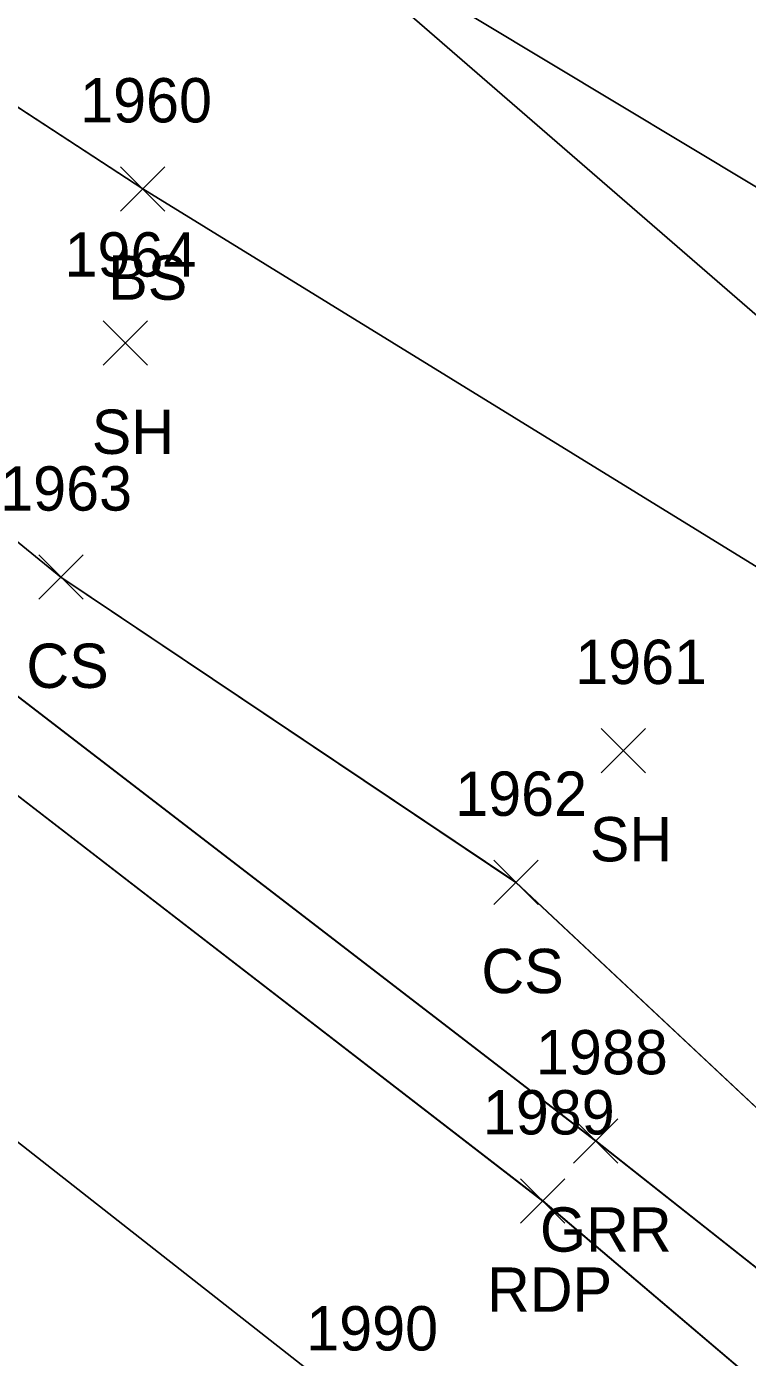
# Model space of a CAD drawing. Extents: x 1415642 to 1422021, y 544543 to 547232.
# Drawn here: x 1416123.6 to 1416156.1, y 546840.3 to 546900.4 of the extents above; entities that cross this region are included whole.
import ezdxf

# ---------------------------------------------------------------- set-up
doc = ezdxf.new("R2010")
doc.units = 0
for name, color, linetype in [('L_A', 7, 'Continuous'), ('L_I', 7, 'Continuous'), ('L_TIC', 7, 'Continuous'), ('LELB', 7, 'Continuous'), ('P_A', 7, 'Continuous'), ('P_I', 7, 'Continuous'), ('P_TIC', 7, 'Continuous'), ('PET', 7, 'Continuous'), ('PRC', 7, 'Continuous'), ('R_A', 7, 'Continuous'), ('R_I', 7, 'Continuous'), ('R_TIC', 7, 'Continuous'), ('RGR', 7, 'Continuous')]:
    doc.layers.add(name, color=color, linetype=linetype)

msp = doc.modelspace()

# ---------------------------------------------------------------- linework, layer by layer
at = {"layer": 'L_TIC'}
for points in [[(1416127.857, 546892.051), (1416129.857, 546894.051)], [(1416129.857, 546892.051), (1416127.857, 546894.051)], [(1416127.067, 546885.094), (1416129.067, 546887.094)], [(1416129.067, 546885.094), (1416127.067, 546887.094)], [(1416124.164, 546874.535), (1416126.164, 546876.535)], [(1416126.164, 546874.535), (1416124.164, 546876.535)], [(1416149.539, 546866.71), (1416151.539, 546868.71)], [(1416151.539, 546866.71), (1416149.539, 546868.71)], [(1416144.693, 546860.764), (1416146.693, 546862.764)], [(1416146.693, 546860.764), (1416144.693, 546862.764)]]:
    msp.add_lwpolyline(points, dxfattribs=at)
at = {"layer": 'LELB'}
for points in [[(1416166.265, 546865.71), (1416159.514, 546874.184), (1416128.857, 546893.051), (1416099.942, 546911.946), (1416080.109, 546927.167), (1416051.607, 546951.273), (1416024.788, 546978.542), (1415989.847, 547005.498), (1415949.916, 547022.61), (1415918.775, 547047.798), (1415880.242, 547071.016), (1415848.802, 547092.398)], [(1416166.265, 546865.71), (1416159.513, 546874.184), (1416128.861, 546893.052), (1416099.946, 546911.942), (1416080.11, 546927.168), (1416051.609, 546951.273), (1416024.792, 546978.539), (1415989.849, 547005.496), (1415949.921, 547022.607), (1415918.779, 547047.795), (1415880.245, 547071.014), (1415848.804, 547092.397)], [(1416210.449, 546810.143), (1416187.238, 546828.497), (1416172.356, 546839.03), (1416162.908, 546845.636), (1416145.696, 546861.763), (1416125.163, 546875.536), (1416093.403, 546901.435), (1416075.184, 546919.901), (1416045.659, 546942.323), (1416039.773, 546946.289), (1416015.879, 546971.975), (1415979.907, 546993.699), (1415946.506, 547018.197), (1415914.221, 547042.269), (1415877.244, 547066.677), (1415845.5, 547087.741)], [(1416210.45, 546810.142), (1416187.236, 546828.498), (1416172.351, 546839.033), (1416162.906, 546845.637), (1416145.693, 546861.764), (1416125.164, 546875.535), (1416093.403, 546901.434), (1416075.185, 546919.898), (1416045.659, 546942.323), (1416039.768, 546946.292), (1416015.881, 546971.972), (1415979.908, 546993.697), (1415946.504, 547018.199), (1415914.218, 547042.271), (1415877.246, 547066.675), (1415845.502, 547087.738)], [(1416165.046, 546879.987), (1416134.798, 546906.212), (1416107.439, 546926.284), (1416090.972, 546938.603)], [(1416165.05, 546879.986), (1416134.799, 546906.211), (1416107.441, 546926.281), (1416090.974, 546938.599)], [(1416186.467, 546882.455), (1416168.837, 546885.751), (1416134.798, 546906.212)], [(1416186.466, 546882.454), (1416168.841, 546885.751), (1416134.799, 546906.211)]]:
    msp.add_lwpolyline(points, dxfattribs=at)
at = {"layer": 'P_TIC'}
for points in [[(1416145.9, 546846.388), (1416147.9, 546848.388)], [(1416147.9, 546846.388), (1416145.9, 546848.388)]]:
    msp.add_lwpolyline(points, dxfattribs=at)
at = {"layer": 'PET'}
for points in [[(1416435.563, 546537.442), (1416408.528, 546574.614), (1416379.536, 546611.972), (1416358.622, 546637.855), (1416320.381, 546681.179), (1416299.042, 546704.617), (1416270.685, 546734.261), (1416256.103, 546749.208), (1416221.421, 546781.441), (1416197.799, 546803.681), (1416167.448, 546829.933), (1416146.9, 546847.388), (1416116.659, 546870.722), (1416088.418, 546892.718), (1416062.975, 546911.586), (1416031.597, 546935.612), (1415998.083, 546959.727), (1415969.063, 546981.933), (1415936.644, 547006.92)], [(1416435.563, 546537.443), (1416408.525, 546574.617), (1416379.538, 546611.971), (1416358.625, 546637.853), (1416320.385, 546681.177), (1416299.042, 546704.618), (1416270.685, 546734.26), (1416256.103, 546749.208), (1416221.419, 546781.443), (1416197.796, 546803.683), (1416167.448, 546829.934), (1416146.904, 546847.385), (1416116.661, 546870.719), (1416088.424, 546892.716), (1416062.98, 546911.583), (1416031.598, 546935.612), (1415998.082, 546959.728), (1415969.067, 546981.931), (1415936.645, 547006.919)]]:
    msp.add_lwpolyline(points, dxfattribs=at)
at = {"layer": 'PRC'}
for points in [[(1416425.288, 546532.234), (1416399.161, 546568.171), (1416370.345, 546605.004), (1416349.982, 546630.027), (1416312.548, 546673.444), (1416291.212, 546696.631), (1416262.577, 546725.994), (1416246.66, 546742.064), (1416214.678, 546772.43), (1416190.398, 546794.673), (1416160.375, 546819.817), (1416139.011, 546837.641), (1416109.604, 546860.715), (1416080.506, 546883.128), (1416051.443, 546902.011), (1416024.837, 546926.071), (1415989.925, 546951.674), (1415962.462, 546973.184)], [(1416425.286, 546532.236), (1416399.162, 546568.17), (1416370.346, 546605.004), (1416349.983, 546630.026), (1416312.547, 546673.445), (1416291.213, 546696.629), (1416262.577, 546725.99), (1416246.657, 546742.061), (1416214.674, 546772.431), (1416190.398, 546794.673), (1416160.375, 546819.819), (1416139.01, 546837.645), (1416109.605, 546860.711), (1416080.506, 546883.127), (1416051.448, 546902.009), (1416024.838, 546926.071), (1415989.923, 546951.676), (1415962.462, 546973.184)]]:
    msp.add_lwpolyline(points, dxfattribs=at)
at = {"layer": 'R_TIC'}
for points in [[(1416148.29, 546849.099), (1416150.29, 546851.099)], [(1416150.29, 546849.099), (1416148.29, 546851.099)]]:
    msp.add_lwpolyline(points, dxfattribs=at)
at = {"layer": 'RGR'}
for points in [[(1416226.79, 546787.66), (1416201.13, 546806.067), (1416168.801, 546834.687), (1416149.29, 546850.099), (1416119.316, 546873.14), (1416091.473, 546896.231), (1416072.683, 546914.463)], [(1416226.789, 546787.661), (1416201.129, 546806.068), (1416168.806, 546834.683), (1416149.293, 546850.097), (1416119.319, 546873.137), (1416091.474, 546896.23), (1416072.684, 546914.463)]]:
    msp.add_lwpolyline(points, dxfattribs=at)

# ---------------------------------------------------------------- texts
at = {"layer": 'L_A'}
for s, p in [('BS', (1416127.298, 546888.051)), ('SH', (1416126.555, 546881.094)), ('CS', (1416123.605, 546870.535)), ('SH', (1416149.027, 546862.71)), ('CS', (1416144.134, 546856.764))]:
    msp.add_text(s, height=2, dxfattribs=at).set_placement(p)
at = {"layer": 'L_I'}
for s, p in [('1960', (1416126.03, 546896.051)), ('1964', (1416125.327, 546889.094)), ('1963', (1416122.424, 546878.535)), ('1961', (1416148.366, 546870.71)), ('1962', (1416142.953, 546864.764))]:
    msp.add_text(s, height=2, dxfattribs=at).set_placement(p)
at = {"layer": 'P_A'}
msp.add_text('RDP', height=2, dxfattribs=at).set_placement((1416144.388, 546842.388))
at = {"layer": 'P_I'}
for s, p in [('1989', (1416144.199, 546850.388)), ('1990', (1416136.232, 546840.641))]:
    msp.add_text(s, height=2, dxfattribs=at).set_placement(p)
at = {"layer": 'R_A'}
msp.add_text('GRR', height=2, dxfattribs=at).set_placement((1416146.778, 546845.099))
at = {"layer": 'R_I'}
msp.add_text('1988', height=2, dxfattribs=at).set_placement((1416146.597, 546853.099))

doc.saveas('drawing.dxf')
